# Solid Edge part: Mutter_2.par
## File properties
Sűrűség: 0,000 kg/m^3
Pontosság: 0,990
Author: ahadarics
Last saved by: ahadarics
Revision: 76
Username: ahadarics
Dokumentum tartalom típus: 0
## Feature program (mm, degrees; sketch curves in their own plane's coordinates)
base feature "unnamed BaseFeature 1"
thread "unnamed Thread 1"
chamfer "unnamed Chamfer 1"
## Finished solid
Body 1: solid body, 13 faces, 24 edges, 12 vertices.
  Faces by surface: plane 8, cone 4, cylinder 1
  Edges by curve: spline 12, circle 6, line 6
Bounding box of the edges (mm): 31.177 x 27.000 x 8.000, from (-15.5885, -13.5, -4) to (15.5885, 13.5, 4).
Cylindrical faces by radius (mm): R10.188 x1
Conical faces (half-angle, radius in mm at the cone's reference point): 45 deg R10.188 x1, 45 deg R11.188 x1, 75 deg R14.5 x2
Planar faces by outward normal: +y 1, +z 1, -y 1, -z 1, oblique 4
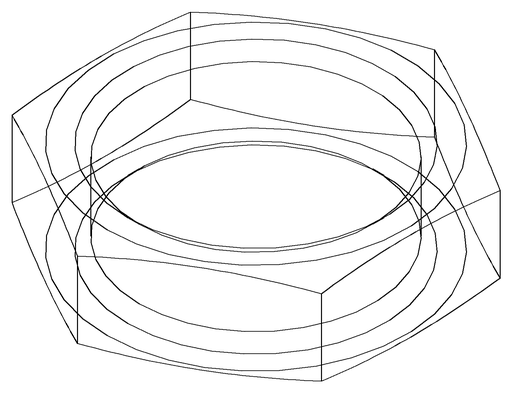
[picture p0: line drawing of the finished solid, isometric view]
